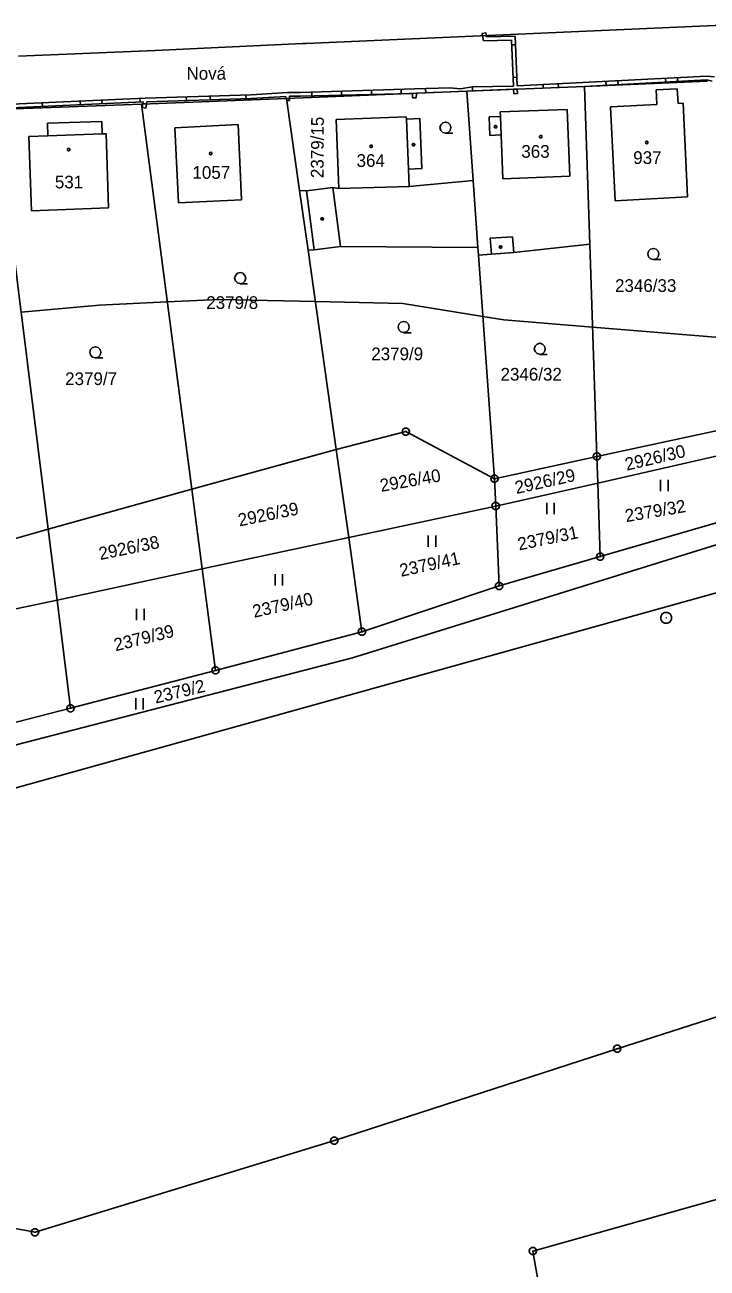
# Model space of a CAD drawing. Extents: x -760611 to -758411, y -1176479 to -1174807.
# Drawn here: x -758816.2 to -758724.8, y -1175101.5 to -1174935 of the extents above; entities that cross this region are included whole.
import ezdxf

# ---------------------------------------------------------------- set-up
doc = ezdxf.new("R2010")
doc.units = 0
for name, color, linetype in [('1', 7, 'Continuous'), ('11', 7, 'Continuous'), ('12', 7, 'Continuous'), ('13', 7, 'Continuous'), ('2', 7, 'Continuous'), ('3', 7, 'Continuous'), ('4', 7, 'Continuous'), ('5', 7, 'Continuous'), ('7', 7, 'Continuous'), ('8', 7, 'Continuous')]:
    doc.layers.add(name, color=color, linetype=linetype)

msp = doc.modelspace()

# ---------------------------------------------------------------- linework, layer by layer
at = {"layer": '1'}
for p, q in [((-758721.71, -1174934.99), (-758778.54, -1174937.47)), ((-758798.76, -1174938.43), (-758779.04, -1174937.49)), ((-758779.04, -1174937.49), (-758778.54, -1174937.47)), ((-758798.76, -1174938.43), (-758817.08, -1174939.2)), ((-758724.75, -1174942.54), (-758741.26, -1174943.23)), ((-758757.02, -1174943.88), (-758781.15, -1174944.87)), ((-758741.26, -1174943.23), (-758757.02, -1174943.88)), ((-758756.16, -1174955.85), (-758757.02, -1174943.88)), ((-758740.54, -1174964.37), (-758741.26, -1174943.23)), ((-758731.63, -1174943.7), (-758728.8, -1174943.55)), ((-758731.53, -1174945.66), (-758731.63, -1174943.7)), ((-758728.8, -1174943.55), (-758728.7, -1174945.51)), ((-758800.62, -1174945.6), (-758820.13, -1174946.33)), ((-758781.15, -1174944.87), (-758800.62, -1174945.6)), ((-758793.87, -1174997.2), (-758800.62, -1174945.6)), ((-758779.41, -1174957.17), (-758781.15, -1174944.87)), ((-758737.74, -1174945.99), (-758731.53, -1174945.66)), ((-758737.11, -1174958.54), (-758737.74, -1174945.99)), ((-758728.7, -1174945.51), (-758728.01, -1174945.47)), ((-758728.01, -1174945.47), (-758727.42, -1174958.04)), ((-758813.09, -1175002.53), (-758820.13, -1174946.33)), ((-758774.52, -1174947.68), (-758765.12, -1174947.3)), ((-758765.12, -1174947.3), (-758765.11, -1174947.6)), ((-758765.11, -1174947.6), (-758763.31, -1174947.52)), ((-758763.31, -1174947.52), (-758763.03, -1174954.23)), ((-758813.2, -1174948.17), (-758805.92, -1174947.92)), ((-758813.14, -1174949.84), (-758813.2, -1174948.17)), ((-758805.92, -1174947.92), (-758805.87, -1174949.59)), ((-758787.66, -1174948.32), (-758796.12, -1174948.77)), ((-758796.12, -1174948.77), (-758795.64, -1174958.83)), ((-758787.18, -1174958.43), (-758787.66, -1174948.32)), ((-758774.14, -1174956.9), (-758774.52, -1174947.68)), ((-758815.68, -1174949.93), (-758813.14, -1174949.84)), ((-758815.33, -1174959.88), (-758815.68, -1174949.93)), ((-758805.87, -1174949.59), (-758805.35, -1174949.57)), ((-758805.35, -1174949.57), (-758805, -1174959.52)), ((-758763.03, -1174954.23), (-758764.83, -1174954.31)), ((-758764.83, -1174954.31), (-758764.74, -1174956.64)), ((-758764.74, -1174956.64), (-758756.16, -1174955.85)), ((-758755.52, -1174964.83), (-758756.16, -1174955.85)), ((-758778.28, -1174965.17), (-758779.41, -1174957.17)), ((-758779.41, -1174957.17), (-758778.49, -1174957.22)), ((-758778.49, -1174957.22), (-758774.94, -1174956.76)), ((-758774.94, -1174956.76), (-758774.14, -1174956.9)), ((-758795.64, -1174958.83), (-758787.18, -1174958.43)), ((-758727.42, -1174958.04), (-758737.11, -1174958.54)), ((-758805, -1174959.52), (-758815.33, -1174959.88)), ((-758778.28, -1174965.17), (-758777.47, -1174965.13)), ((-758774.5, -1174991.85), (-758778.28, -1174965.17)), ((-758777.47, -1174965.13), (-758773.92, -1174964.68)), ((-758773.92, -1174964.68), (-758755.52, -1174964.83)), ((-758755.45, -1174965.82), (-758755.52, -1174964.83)), ((-758753.72, -1174965.69), (-758755.45, -1174965.82)), ((-758755.45, -1174965.82), (-758753.3, -1174995.8)), ((-758750.73, -1174965.48), (-758753.72, -1174965.69)), ((-758740.54, -1174964.37), (-758750.73, -1174965.48)), ((-758739.58, -1174992.81), (-758740.54, -1174964.37)), ((-758722.59, -1174989.16), (-758739.58, -1174992.81)), ((-758765.18, -1174989.47), (-758774.5, -1174991.85)), ((-758753.3, -1174995.8), (-758765.18, -1174989.47)), ((-758774.5, -1174991.85), (-758793.87, -1174997.2)), ((-758772.84, -1175003.67), (-758774.5, -1174991.85)), ((-758722.43, -1174992.51), (-758739.46, -1174996.37)), ((-758739.58, -1174992.81), (-758753.3, -1174995.8)), ((-758739.46, -1174996.37), (-758739.58, -1174992.81)), ((-758691.55, -1174994.68), (-758772.34, -1175019.78)), ((-758753.14, -1174999.46), (-758753.3, -1174995.8)), ((-758813.09, -1175002.53), (-758793.87, -1174997.2)), ((-758793.87, -1174997.2), (-758792.47, -1175007.87)), ((-758739.46, -1174996.37), (-758753.14, -1174999.46)), ((-758739.13, -1175006.22), (-758739.46, -1174996.37)), ((-758683.75, -1175000), (-758783.55, -1175027.78)), ((-758753.14, -1174999.46), (-758772.84, -1175003.67)), ((-758752.68, -1175010.15), (-758753.14, -1174999.46)), ((-758839.93, -1175010.15), (-758813.09, -1175002.53)), ((-758811.91, -1175012.03), (-758813.09, -1175002.53)), ((-758722.03, -1175001.26), (-758739.13, -1175006.22)), ((-758772.84, -1175003.67), (-758792.47, -1175007.87)), ((-758771.06, -1175016.29), (-758772.84, -1175003.67)), ((-758739.13, -1175006.22), (-758752.68, -1175010.15)), ((-758792.47, -1175007.87), (-758811.91, -1175012.03)), ((-758792.47, -1175007.87), (-758790.68, -1175021.48)), ((-758771.06, -1175016.29), (-758752.68, -1175010.15)), ((-758811.91, -1175012.03), (-758838.91, -1175017.81)), ((-758810.11, -1175026.53), (-758811.91, -1175012.03)), ((-758790.68, -1175021.48), (-758771.06, -1175016.29)), ((-758772.34, -1175019.78), (-758839.22, -1175037.05)), ((-758810.11, -1175026.53), (-758790.68, -1175021.48)), ((-758836.85, -1175033.36), (-758810.11, -1175026.53)), ((-758783.55, -1175027.78), (-758837.6, -1175042.81)), ((-758637.64, -1175040.23), (-758736.85, -1175072.13)), ((-758630.01, -1175066.05), (-758748.15, -1175099.24)), ((-758736.85, -1175072.13), (-758774.76, -1175084.44)), ((-758774.76, -1175084.44), (-758814.87, -1175096.72)), ((-758814.87, -1175096.72), (-758836.86, -1175092.56)), ((-758748.15, -1175099.24), (-758743.15, -1175127.6))]:
    msp.add_line(p, q, dxfattribs=at)
at = {"layer": '11'}
msp.add_lwpolyline([(-758723.16, -1174976.86), (-758740.17, -1174975.47), (-758752.03, -1174974.5), (-758754.86, -1174974.04), (-758765.59, -1174972.32), (-758777.3, -1174972.06), (-758790.18, -1174971.77), (-758797.15, -1174972.1), (-758806.29, -1174972.54), (-758816.73, -1174973.48)], dxfattribs=at)
at = {"layer": '12'}
for p, q in [((-758731.63, -1174943.7), (-758728.8, -1174943.55)), ((-758731.53, -1174945.66), (-758731.63, -1174943.7)), ((-758728.8, -1174943.55), (-758728.7, -1174945.51)), ((-758737.74, -1174945.99), (-758731.53, -1174945.66)), ((-758737.11, -1174958.54), (-758737.74, -1174945.99)), ((-758728.7, -1174945.51), (-758728.01, -1174945.47)), ((-758728.01, -1174945.47), (-758727.42, -1174958.04)), ((-758774.52, -1174947.68), (-758765.12, -1174947.3)), ((-758765.12, -1174947.3), (-758765.11, -1174947.6)), ((-758765.11, -1174947.6), (-758764.83, -1174954.31)), ((-758752.53, -1174946.66), (-758743.57, -1174946.31)), ((-758752.5, -1174947.27), (-758752.53, -1174946.66)), ((-758752.5, -1174947.27), (-758752.41, -1174949.74)), ((-758743.57, -1174946.31), (-758743.22, -1174955.27)), ((-758787.66, -1174948.32), (-758796.12, -1174948.77)), ((-758796.12, -1174948.77), (-758795.64, -1174958.83)), ((-758787.18, -1174958.43), (-758787.66, -1174948.32)), ((-758774.14, -1174956.9), (-758774.52, -1174947.68)), ((-758815.68, -1174949.93), (-758813.14, -1174949.84)), ((-758815.33, -1174959.88), (-758815.68, -1174949.93)), ((-758805.87, -1174949.59), (-758813.14, -1174949.84)), ((-758805.87, -1174949.59), (-758805.35, -1174949.57)), ((-758805.35, -1174949.57), (-758805, -1174959.52)), ((-758752.18, -1174955.61), (-758752.41, -1174949.74)), ((-758764.83, -1174954.31), (-758764.74, -1174956.64)), ((-758743.22, -1174955.27), (-758752.18, -1174955.61)), ((-758764.74, -1174956.64), (-758774.14, -1174956.9)), ((-758795.64, -1174958.83), (-758787.18, -1174958.43)), ((-758727.42, -1174958.04), (-758737.11, -1174958.54)), ((-758805, -1174959.52), (-758815.33, -1174959.88))]:
    msp.add_line(p, q, dxfattribs=at)
at = {"layer": '13'}
for p, q in [((-758754.9, -1174936.44), (-758754.39, -1174936.42)), ((-758754.79, -1174937.12), (-758754.9, -1174936.44)), ((-758751.02, -1174937.02), (-758754.79, -1174937.12)), ((-758754.39, -1174936.42), (-758754.37, -1174936.6)), ((-758754.37, -1174936.6), (-758750.54, -1174936.5)), ((-758750.76, -1174943.18), (-758751.02, -1174937.02)), ((-758750.99, -1174937.68), (-758750.49, -1174937.66)), ((-758750.54, -1174936.5), (-758750.26, -1174943.16)), ((-758750.31, -1174942), (-758750.81, -1174942.02)), ((-758750.26, -1174943.16), (-758724.86, -1174941.87)), ((-758724.86, -1174942.37), (-758741.26, -1174943.23)), ((-758738.34, -1174943.08), (-758738.37, -1174942.58)), ((-758736.78, -1174942.48), (-758736.75, -1174942.97)), ((-758730.35, -1174942.66), (-758730.38, -1174942.16)), ((-758728.79, -1174942.07), (-758728.76, -1174942.57)), ((-758724.86, -1174941.87), (-758723.84, -1174941.95)), ((-758724.12, -1174942.51), (-758724.86, -1174942.37)), ((-758785.92, -1174944.37), (-758781.04, -1174944.05)), ((-758781.04, -1174944.05), (-758779.31, -1174944.06)), ((-758779.31, -1174944.06), (-758764.02, -1174943.58)), ((-758764.27, -1174944.18), (-758779.31, -1174944.56)), ((-758777.77, -1174944.52), (-758777.78, -1174944.02)), ((-758773.81, -1174943.89), (-758773.8, -1174944.39)), ((-758769.77, -1174944.32), (-758769.78, -1174943.82)), ((-758765.82, -1174943.64), (-758765.8, -1174944.14)), ((-758764.28, -1174944.75), (-758764.27, -1174944.18)), ((-758763.77, -1174944.16), (-758764.27, -1174944.18)), ((-758764.27, -1174944.18), (-758763.77, -1174944.16)), ((-758764.02, -1174943.58), (-758759.29, -1174943.42)), ((-758763.77, -1174944.16), (-758763.78, -1174944.77)), ((-758757.02, -1174943.88), (-758763.77, -1174944.16)), ((-758762.52, -1174944.11), (-758762.54, -1174943.61)), ((-758759.29, -1174943.42), (-758757.84, -1174943.54)), ((-758757.84, -1174943.54), (-758756.28, -1174943.3)), ((-758750.74, -1174943.62), (-758757.02, -1174943.88)), ((-758756.28, -1174943.3), (-758750.76, -1174943.18)), ((-758756.24, -1174943.85), (-758756.26, -1174943.35)), ((-758750.24, -1174943.6), (-758750.74, -1174943.62)), ((-758750.74, -1174943.62), (-758750.24, -1174943.6)), ((-758750.7, -1174944.24), (-758750.74, -1174943.62)), ((-758750.2, -1174944.2), (-758750.7, -1174944.24)), ((-758741.26, -1174943.23), (-758750.24, -1174943.6)), ((-758750.24, -1174943.6), (-758750.2, -1174944.2)), ((-758746.76, -1174943.46), (-758746.78, -1174942.96)), ((-758744.77, -1174942.88), (-758744.74, -1174943.38)), ((-758838.28, -1174946.57), (-758800.1, -1174944.8)), ((-758800.39, -1174945.31), (-758820.62, -1174946.23)), ((-758813.88, -1174945.92), (-758813.9, -1174945.42)), ((-758808.81, -1174945.2), (-758808.79, -1174945.7)), ((-758805.88, -1174945.56), (-758805.91, -1174945.06)), ((-758800.82, -1174944.83), (-758800.8, -1174945.33)), ((-758800.51, -1174946.05), (-758800.43, -1174945.59)), ((-758800.43, -1174945.59), (-758800.39, -1174945.31)), ((-758799.92, -1174945.57), (-758800.43, -1174945.59)), ((-758800.1, -1174944.8), (-758785.92, -1174944.37)), ((-758799.88, -1174945.29), (-758799.92, -1174945.57)), ((-758785.9, -1174944.87), (-758799.88, -1174945.29)), ((-758794.6, -1174944.63), (-758794.59, -1174945.13)), ((-758791.4, -1174945.04), (-758791.41, -1174944.54)), ((-758786.61, -1174944.39), (-758786.59, -1174944.89)), ((-758781.28, -1174944.57), (-758785.9, -1174944.87)), ((-758781.28, -1174944.87), (-758781.28, -1174944.57)), ((-758781.15, -1174944.87), (-758780.78, -1174944.85)), ((-758781.12, -1174945.1), (-758781.15, -1174944.87)), ((-758780.78, -1174945.1), (-758781.12, -1174945.1)), ((-758779.31, -1174944.56), (-758780.78, -1174944.55)), ((-758780.78, -1174944.55), (-758780.78, -1174944.85)), ((-758780.78, -1174944.85), (-758780.78, -1174945.1)), ((-758763.78, -1174944.77), (-758764.28, -1174944.75))]:
    msp.add_line(p, q, dxfattribs=at)
for points in [[(-758754.9, -1174936.44), (-758754.94, -1174936.13), (-758754.45, -1174936.06), (-758754.39, -1174936.42)], [(-758800.43, -1174945.59), (-758799.92, -1174945.57), (-758800.01, -1174946.13), (-758800.51, -1174946.05)]]:
    msp.add_lwpolyline(points, close=True, dxfattribs=at)
msp.add_lwpolyline([(-758780.78, -1174944.85), (-758781.15, -1174944.87), (-758781.28, -1174944.87)], dxfattribs=at)
at = {"layer": '3'}
for p, q in [((-758731.05, -1174995.93), (-758731.05, -1174997.43)), ((-758730.05, -1174997.43), (-758730.05, -1174995.93)), ((-758746.3, -1174999.03), (-758746.3, -1175000.53)), ((-758745.3, -1175000.53), (-758745.3, -1174999.03)), ((-758762.17, -1175003.39), (-758762.17, -1175004.89)), ((-758761.17, -1175004.89), (-758761.17, -1175003.39)), ((-758782.7, -1175008.59), (-758782.7, -1175010.09)), ((-758781.7, -1175010.09), (-758781.7, -1175008.59)), ((-758801.26, -1175013.23), (-758801.26, -1175014.73)), ((-758800.26, -1175014.73), (-758800.26, -1175013.23)), ((-758801.38, -1175025.18), (-758801.38, -1175026.68)), ((-758800.38, -1175026.68), (-758800.38, -1175025.18))]:
    msp.add_line(p, q, dxfattribs=at)
for points in [[(-758759.86, -1174949.49), (-758760.24, -1174949.39), (-758760.51, -1174949.12), (-758760.61, -1174948.75), (-758760.51, -1174948.38), (-758760.24, -1174948.11), (-758759.87, -1174948.01), (-758759.5, -1174948.11), (-758759.23, -1174948.38), (-758759.13, -1174948.76), (-758759.23, -1174949.14), (-758759.5, -1174949.41), (-758759.88, -1174949.51), (-758758.88, -1174949.51)], [(-758732, -1174966.41), (-758732.38, -1174966.31), (-758732.65, -1174966.04), (-758732.75, -1174965.67), (-758732.65, -1174965.3), (-758732.38, -1174965.03), (-758732.01, -1174964.93), (-758731.64, -1174965.03), (-758731.37, -1174965.3), (-758731.27, -1174965.68), (-758731.37, -1174966.06), (-758731.64, -1174966.33), (-758732.02, -1174966.43), (-758731.02, -1174966.43)], [(-758787.37, -1174969.65), (-758787.75, -1174969.55), (-758788.02, -1174969.28), (-758788.12, -1174968.91), (-758788.02, -1174968.54), (-758787.75, -1174968.27), (-758787.38, -1174968.17), (-758787.01, -1174968.27), (-758786.74, -1174968.54), (-758786.64, -1174968.92), (-758786.74, -1174969.3), (-758787.01, -1174969.57), (-758787.39, -1174969.67), (-758786.39, -1174969.67)], [(-758765.46, -1174976.2), (-758765.84, -1174976.1), (-758766.11, -1174975.83), (-758766.21, -1174975.46), (-758766.11, -1174975.09), (-758765.84, -1174974.82), (-758765.47, -1174974.72), (-758765.1, -1174974.82), (-758764.83, -1174975.09), (-758764.73, -1174975.47), (-758764.83, -1174975.85), (-758765.1, -1174976.12), (-758765.48, -1174976.22), (-758764.48, -1174976.22)], [(-758806.77, -1174979.58), (-758807.15, -1174979.48), (-758807.42, -1174979.21), (-758807.52, -1174978.84), (-758807.42, -1174978.47), (-758807.15, -1174978.2), (-758806.78, -1174978.1), (-758806.41, -1174978.2), (-758806.14, -1174978.47), (-758806.04, -1174978.85), (-758806.14, -1174979.23), (-758806.41, -1174979.5), (-758806.79, -1174979.6), (-758805.79, -1174979.6)], [(-758747.22, -1174979.12), (-758747.6, -1174979.02), (-758747.87, -1174978.75), (-758747.97, -1174978.38), (-758747.87, -1174978.01), (-758747.6, -1174977.74), (-758747.23, -1174977.64), (-758746.86, -1174977.74), (-758746.59, -1174978.01), (-758746.49, -1174978.39), (-758746.59, -1174978.77), (-758746.86, -1174979.04), (-758747.24, -1174979.14), (-758746.24, -1174979.14)]]:
    msp.add_lwpolyline(points, dxfattribs=at)
at = {"layer": '4'}
for p, q in [((-758765.11, -1174947.6), (-758764.83, -1174954.31)), ((-758754, -1174947.33), (-758752.5, -1174947.27)), ((-758753.91, -1174949.8), (-758754, -1174947.33)), ((-758752.53, -1174946.66), (-758743.57, -1174946.31)), ((-758752.5, -1174947.27), (-758752.53, -1174946.66)), ((-758752.5, -1174947.27), (-758752.41, -1174949.74)), ((-758743.57, -1174946.31), (-758743.22, -1174955.27)), ((-758805.87, -1174949.59), (-758813.14, -1174949.84)), ((-758752.41, -1174949.74), (-758753.91, -1174949.8)), ((-758752.18, -1174955.61), (-758752.41, -1174949.74)), ((-758743.22, -1174955.27), (-758752.18, -1174955.61)), ((-758777.47, -1174965.13), (-758778.49, -1174957.22)), ((-758774.94, -1174956.76), (-758773.92, -1174964.68)), ((-758764.74, -1174956.64), (-758774.14, -1174956.9)), ((-758750.87, -1174963.38), (-758753.86, -1174963.58)), ((-758753.86, -1174963.58), (-758753.72, -1174965.69)), ((-758750.73, -1174965.48), (-758750.87, -1174963.38))]:
    msp.add_line(p, q, dxfattribs=at)
at = {"layer": '5'}
for points in [[(-758753.07, -1174948.49), (-758752.98, -1174948.64), (-758753.07, -1174948.79), (-758753.25, -1174948.79), (-758753.34, -1174948.64), (-758753.25, -1174948.49)], [(-758764.05, -1174950.88), (-758763.96, -1174951.03), (-758764.05, -1174951.18), (-758764.23, -1174951.18), (-758764.32, -1174951.03), (-758764.23, -1174950.88)], [(-758747.1, -1174949.81), (-758747, -1174949.83), (-758746.95, -1174949.92), (-758746.93, -1174949.98), (-758746.95, -1174950.07), (-758747.03, -1174950.14), (-758747.1, -1174950.15), (-758747.19, -1174950.12), (-758747.25, -1174950.06), (-758747.27, -1174949.98), (-758747.25, -1174949.89), (-758747.17, -1174949.82)], [(-758732.89, -1174950.58), (-758732.79, -1174950.6), (-758732.74, -1174950.69), (-758732.72, -1174950.75), (-758732.74, -1174950.84), (-758732.82, -1174950.91), (-758732.89, -1174950.92), (-758732.98, -1174950.89), (-758733.04, -1174950.83), (-758733.06, -1174950.75), (-758733.04, -1174950.66), (-758732.96, -1174950.59)], [(-758810.36, -1174951.52), (-758810.26, -1174951.54), (-758810.21, -1174951.63), (-758810.19, -1174951.69), (-758810.21, -1174951.78), (-758810.29, -1174951.85), (-758810.36, -1174951.86), (-758810.45, -1174951.83), (-758810.51, -1174951.77), (-758810.53, -1174951.69), (-758810.51, -1174951.6), (-758810.43, -1174951.53)], [(-758791.33, -1174952.06), (-758791.23, -1174952.08), (-758791.18, -1174952.17), (-758791.16, -1174952.23), (-758791.18, -1174952.32), (-758791.26, -1174952.39), (-758791.33, -1174952.4), (-758791.42, -1174952.37), (-758791.48, -1174952.31), (-758791.5, -1174952.23), (-758791.48, -1174952.14), (-758791.4, -1174952.07)], [(-758769.83, -1174951.09), (-758769.73, -1174951.11), (-758769.68, -1174951.2), (-758769.66, -1174951.26), (-758769.68, -1174951.35), (-758769.76, -1174951.42), (-758769.83, -1174951.43), (-758769.92, -1174951.4), (-758769.98, -1174951.34), (-758770, -1174951.26), (-758769.98, -1174951.17), (-758769.9, -1174951.1)], [(-758776.3, -1174960.82), (-758776.21, -1174960.97), (-758776.3, -1174961.12), (-758776.48, -1174961.12), (-758776.57, -1174960.97), (-758776.48, -1174960.82)], [(-758752.39, -1174964.59), (-758752.3, -1174964.74), (-758752.39, -1174964.89), (-758752.57, -1174964.89), (-758752.66, -1174964.74), (-758752.57, -1174964.59)]]:
    msp.add_lwpolyline(points, close=True, dxfattribs=at)
at = {"layer": '8'}
for p, q in [((-758765.3, -1174989.47), (-758765.06, -1174989.47)), ((-758739.7, -1174992.81), (-758739.46, -1174992.81)), ((-758753.42, -1174995.8), (-758753.18, -1174995.8)), ((-758753.26, -1174999.46), (-758753.02, -1174999.46)), ((-758739.25, -1175006.22), (-758739.01, -1175006.22)), ((-758752.8, -1175010.15), (-758752.56, -1175010.15)), ((-758730.35, -1175014.41), (-758730.25, -1175014.41)), ((-758771.18, -1175016.29), (-758770.94, -1175016.29)), ((-758790.8, -1175021.48), (-758790.56, -1175021.48)), ((-758810.23, -1175026.53), (-758809.99, -1175026.53)), ((-758736.97, -1175072.13), (-758736.73, -1175072.13)), ((-758774.88, -1175084.44), (-758774.64, -1175084.44)), ((-758814.99, -1175096.72), (-758814.75, -1175096.72)), ((-758748.27, -1175099.24), (-758748.03, -1175099.24))]:
    msp.add_line(p, q, dxfattribs=at)
for points in [[(-758765.03, -1174988.99), (-758764.78, -1174989.17), (-758764.68, -1174989.46), (-758764.78, -1174989.75), (-758765.03, -1174989.93), (-758765.34, -1174989.93), (-758765.59, -1174989.75), (-758765.69, -1174989.46), (-758765.59, -1174989.17), (-758765.34, -1174988.99)], [(-758739.43, -1174992.33), (-758739.18, -1174992.51), (-758739.08, -1174992.8), (-758739.18, -1174993.09), (-758739.43, -1174993.27), (-758739.74, -1174993.27), (-758739.99, -1174993.09), (-758740.09, -1174992.8), (-758739.99, -1174992.51), (-758739.74, -1174992.33)], [(-758753.15, -1174995.32), (-758752.9, -1174995.5), (-758752.8, -1174995.79), (-758752.9, -1174996.08), (-758753.15, -1174996.26), (-758753.46, -1174996.26), (-758753.71, -1174996.08), (-758753.81, -1174995.79), (-758753.71, -1174995.5), (-758753.46, -1174995.32)], [(-758752.99, -1174998.98), (-758752.74, -1174999.16), (-758752.64, -1174999.45), (-758752.74, -1174999.74), (-758752.99, -1174999.92), (-758753.3, -1174999.92), (-758753.55, -1174999.74), (-758753.65, -1174999.45), (-758753.55, -1174999.16), (-758753.3, -1174998.98)], [(-758738.98, -1175005.74), (-758738.73, -1175005.92), (-758738.63, -1175006.21), (-758738.73, -1175006.5), (-758738.98, -1175006.68), (-758739.29, -1175006.68), (-758739.54, -1175006.5), (-758739.64, -1175006.21), (-758739.54, -1175005.92), (-758739.29, -1175005.74)], [(-758752.53, -1175009.67), (-758752.28, -1175009.85), (-758752.18, -1175010.14), (-758752.28, -1175010.43), (-758752.53, -1175010.61), (-758752.84, -1175010.61), (-758753.09, -1175010.43), (-758753.19, -1175010.14), (-758753.09, -1175009.85), (-758752.84, -1175009.67)], [(-758730.11, -1175013.69), (-758729.77, -1175013.88), (-758729.58, -1175014.22), (-758729.58, -1175014.61), (-758729.77, -1175014.95), (-758730.11, -1175015.14), (-758730.5, -1175015.14), (-758730.84, -1175014.95), (-758731.03, -1175014.61), (-758731.03, -1175014.22), (-758730.84, -1175013.88), (-758730.5, -1175013.69)], [(-758770.91, -1175015.81), (-758770.66, -1175015.99), (-758770.56, -1175016.28), (-758770.66, -1175016.57), (-758770.91, -1175016.75), (-758771.22, -1175016.75), (-758771.47, -1175016.57), (-758771.57, -1175016.28), (-758771.47, -1175015.99), (-758771.22, -1175015.81)], [(-758790.53, -1175021), (-758790.28, -1175021.18), (-758790.18, -1175021.47), (-758790.28, -1175021.76), (-758790.53, -1175021.94), (-758790.84, -1175021.94), (-758791.09, -1175021.76), (-758791.19, -1175021.47), (-758791.09, -1175021.18), (-758790.84, -1175021)], [(-758809.96, -1175026.05), (-758809.71, -1175026.23), (-758809.61, -1175026.52), (-758809.71, -1175026.81), (-758809.96, -1175026.99), (-758810.27, -1175026.99), (-758810.52, -1175026.81), (-758810.62, -1175026.52), (-758810.52, -1175026.23), (-758810.27, -1175026.05)], [(-758736.7, -1175071.65), (-758736.45, -1175071.83), (-758736.35, -1175072.12), (-758736.45, -1175072.41), (-758736.7, -1175072.59), (-758737.01, -1175072.59), (-758737.26, -1175072.41), (-758737.36, -1175072.12), (-758737.26, -1175071.83), (-758737.01, -1175071.65)], [(-758774.61, -1175083.96), (-758774.36, -1175084.14), (-758774.26, -1175084.43), (-758774.36, -1175084.72), (-758774.61, -1175084.9), (-758774.92, -1175084.9), (-758775.17, -1175084.72), (-758775.27, -1175084.43), (-758775.17, -1175084.14), (-758774.92, -1175083.96)], [(-758814.72, -1175096.24), (-758814.47, -1175096.42), (-758814.37, -1175096.71), (-758814.47, -1175097), (-758814.72, -1175097.18), (-758815.03, -1175097.18), (-758815.28, -1175097), (-758815.38, -1175096.71), (-758815.28, -1175096.42), (-758815.03, -1175096.24)], [(-758748, -1175098.76), (-758747.75, -1175098.94), (-758747.65, -1175099.23), (-758747.75, -1175099.52), (-758748, -1175099.7), (-758748.31, -1175099.7), (-758748.56, -1175099.52), (-758748.66, -1175099.23), (-758748.56, -1175098.94), (-758748.31, -1175098.76)]]:
    msp.add_lwpolyline(points, close=True, dxfattribs=at)

# ---------------------------------------------------------------- texts
at = {"layer": '2'}
for s, rotation, p in [('2379/15', 89.6679, (-758776.21, -1174955.52)), ('2926/30', 13.2926, (-758735.58, -1174994.72)), ('2926/40', 10.0268, (-758768.49, -1174997.55)), ('2926/29', 12.4905, (-758750.36, -1174997.84)), ('2926/39', 11.4019, (-758787.48, -1175002.18)), ('2379/32', 9.6257, (-758735.66, -1175001.61)), ('2379/31', 11.7456, (-758750, -1175005.4)), ('2926/38', 11.5165, (-758806.14, -1175006.68)), ('2379/41', 12.204, (-758765.82, -1175008.93)), ('2379/40', 12.6051, (-758785.51, -1175014.42)), ('2379/39', 14.0375, (-758804.07, -1175018.91)), ('2379/2', 13.4645, (-758798.7, -1175025.91))]:
    msp.add_text(s, height=1.7, rotation=rotation, dxfattribs=at).set_placement(p)
for s, p in [('364', (-758771.78, -1174954.01)), ('363', (-758749.7, -1174952.79)), ('937', (-758734.71, -1174953.62)), ('1057', (-758793.77, -1174955.61)), ('531', (-758812.21, -1174956.89)), ('2346/33', (-758737.15, -1174970.76)), ('2379/8', (-758791.92, -1174973.04)), ('2379/9', (-758769.81, -1174979.91)), ('2346/32', (-758752.49, -1174982.64)), ('2379/7', (-758810.83, -1174983.24))]:
    msp.add_text(s, height=1.7, dxfattribs=at).set_placement(p)
at = {"layer": '7'}
msp.add_text('Nová', height=1.7, dxfattribs=at).set_placement((-758794.57, -1174942.34))

doc.saveas('drawing.dxf')
